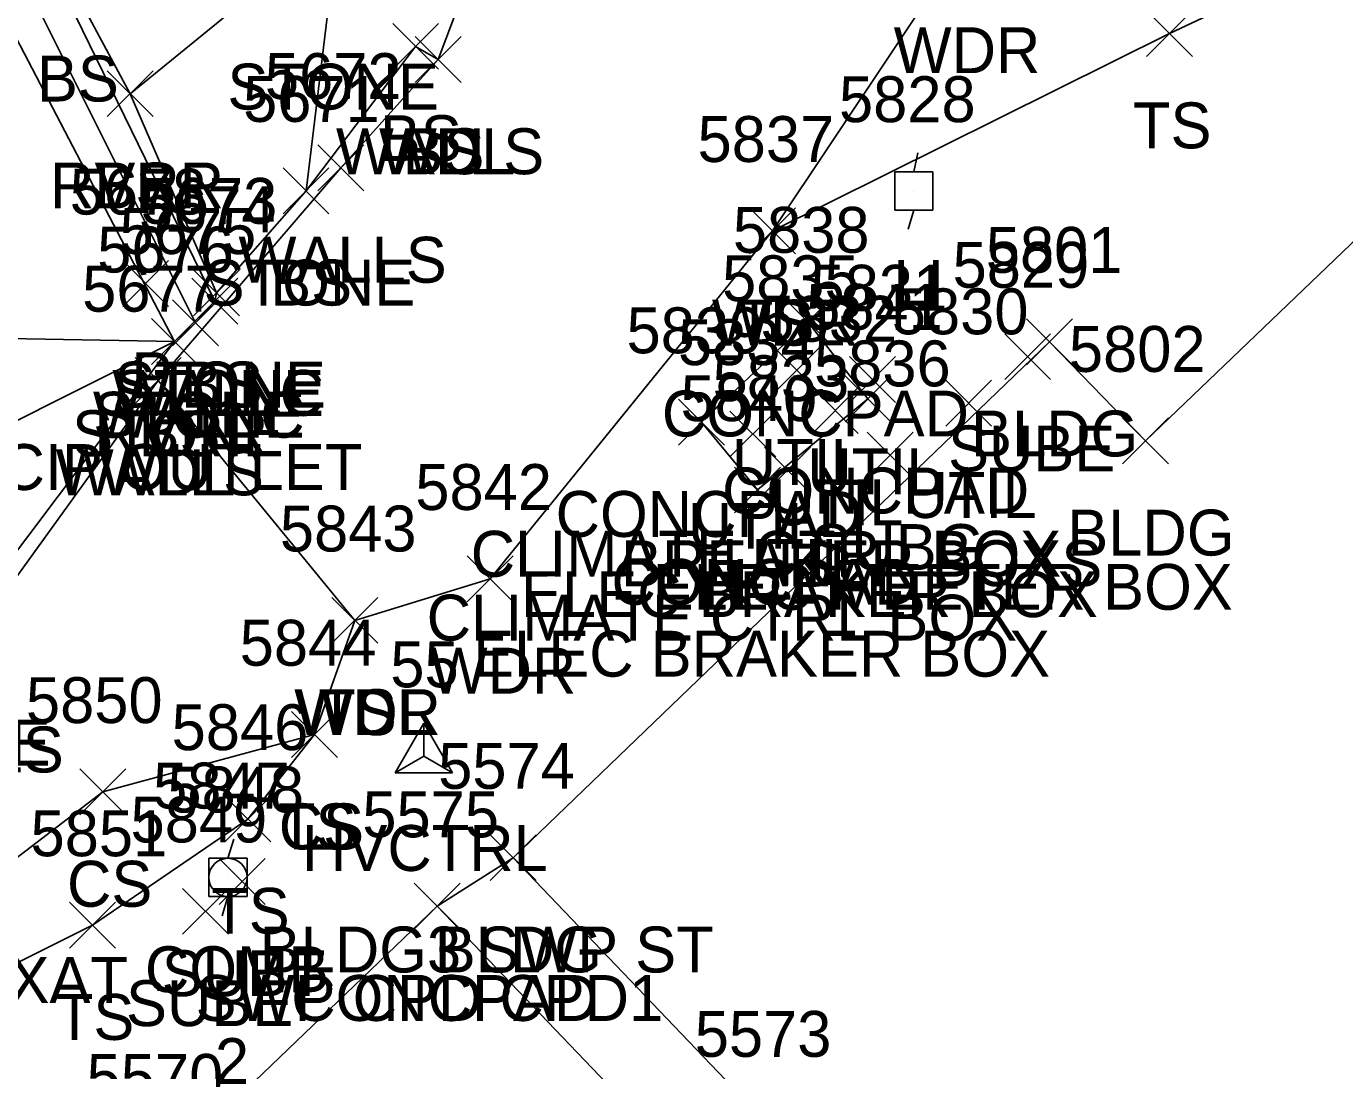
# Model space of a CAD drawing. Extents: x 1618146 to 1620418, y 640749 to 641927.
# Drawn here: x 1620120.5 to 1620177.9, y 641215.6 to 641261.1 of the extents above; entities that cross this region are included whole.
import ezdxf

# ---------------------------------------------------------------- set-up
doc = ezdxf.new("R2010")
doc.units = 0
for name, color, linetype in [('C_A', 7, 'Continuous'), ('C_C', 7, 'Continuous'), ('C_I', 7, 'Continuous'), ('CPSM', 7, 'Continuous'), ('D_A', 7, 'Continuous'), ('D_C', 7, 'Continuous'), ('D_I', 7, 'Continuous'), ('D_TIC', 7, 'Continuous'), ('L_A', 7, 'Continuous'), ('L_I', 7, 'Continuous'), ('L_TIC', 7, 'Continuous'), ('LASF', 7, 'Continuous'), ('LAWA', 7, 'Continuous'), ('LAWE', 7, 'Continuous'), ('LBC', 7, 'Continuous'), ('LELB', 7, 'Continuous'), ('LS', 7, 'Continuous'), ('LW', 7, 'Continuous'), ('LWS', 7, 'Continuous'), ('R_A', 7, 'Continuous'), ('R_I', 7, 'Continuous'), ('R_TIC', 7, 'Continuous'), ('RSW', 7, 'Continuous'), ('U_A', 7, 'Continuous'), ('U_C', 7, 'Continuous'), ('U_I', 7, 'Continuous'), ('U_TIC', 7, 'Continuous'), ('UDEFAULT', 7, 'Continuous'), ('ULP', 7, 'Continuous'), ('UP', 7, 'Continuous')]:
    doc.layers.add(name, color=color, linetype=linetype)

msp = doc.modelspace()

# ---------------------------------------------------------------- linework, layer by layer
at = {"layer": 'CPSM'}
for p, q in [((1620136.538, 641228.601), (1620137.788, 641230.766)), ((1620139.038, 641228.601), (1620137.788, 641230.766)), ((1620137.788, 641229.322), (1620137.788, 641230.766)), ((1620136.538, 641228.601), (1620137.788, 641229.322)), ((1620137.788, 641229.322), (1620137.788, 641229.322)), ((1620137.788, 641229.322), (1620139.038, 641228.601)), ((1620136.538, 641228.601), (1620139.038, 641228.601))]:
    msp.add_line(p, q, dxfattribs=at)
at = {"layer": 'D_TIC'}
for points in [[(1620124.672, 641248.918), (1620126.672, 641250.918)], [(1620126.672, 641248.918), (1620124.672, 641250.918)]]:
    msp.add_lwpolyline(points, dxfattribs=at)
at = {"layer": 'L_TIC'}
for points in [[(1620169.25, 641259.802), (1620171.25, 641261.802)], [(1620171.25, 641259.802), (1620169.25, 641261.802)], [(1620136.427, 641259.244), (1620138.427, 641261.244)], [(1620138.427, 641259.244), (1620136.427, 641261.244)], [(1620137.412, 641258.674), (1620139.412, 641260.674)], [(1620139.412, 641258.674), (1620137.412, 641260.674)], [(1620137.412, 641258.674), (1620139.412, 641260.674)], [(1620139.412, 641258.674), (1620137.412, 641260.674)], [(1620137.412, 641258.674), (1620139.412, 641260.674)], [(1620139.412, 641258.674), (1620137.412, 641260.674)], [(1620123.997, 641257.183), (1620125.997, 641259.183)], [(1620125.997, 641257.183), (1620123.997, 641259.183)], [(1620123.997, 641257.183), (1620125.997, 641259.183)], [(1620125.997, 641257.183), (1620123.997, 641259.183)], [(1620133.17, 641253.949), (1620135.17, 641255.949)], [(1620135.17, 641253.949), (1620133.17, 641255.949)], [(1620131.653, 641252.954), (1620133.653, 641254.954)], [(1620133.653, 641252.954), (1620131.653, 641254.954)], [(1620131.653, 641252.954), (1620133.653, 641254.954)], [(1620133.653, 641252.954), (1620131.653, 641254.954)], [(1620151.961, 641251.207), (1620153.961, 641253.207)], [(1620153.961, 641251.207), (1620151.961, 641253.207)], [(1620151.961, 641251.207), (1620153.961, 641253.207)], [(1620153.961, 641251.207), (1620151.961, 641253.207)], [(1620127.684, 641248.148), (1620129.684, 641250.148)], [(1620129.684, 641248.148), (1620127.684, 641250.148)], [(1620127.684, 641248.148), (1620129.684, 641250.148)], [(1620129.684, 641248.148), (1620127.684, 641250.148)], [(1620127.761, 641248.512), (1620129.761, 641250.512)], [(1620129.761, 641248.512), (1620127.761, 641250.512)], [(1620127.761, 641248.512), (1620129.761, 641250.512)], [(1620129.761, 641248.512), (1620127.761, 641250.512)], [(1620126.842, 641247.197), (1620128.842, 641249.197)], [(1620128.842, 641247.197), (1620126.842, 641249.197)], [(1620126.842, 641247.197), (1620128.842, 641249.197)], [(1620128.842, 641247.197), (1620126.842, 641249.197)], [(1620153.5, 641247.251), (1620155.5, 641249.251)], [(1620155.5, 641247.251), (1620153.5, 641249.251)], [(1620153.5, 641247.251), (1620155.5, 641249.251)], [(1620155.5, 641247.251), (1620153.5, 641249.251)], [(1620125.924, 641246.392), (1620127.924, 641248.392)], [(1620127.924, 641246.392), (1620125.924, 641248.392)], [(1620125.924, 641246.392), (1620127.924, 641248.392)], [(1620127.924, 641246.392), (1620125.924, 641248.392)], [(1620125.924, 641246.392), (1620127.924, 641248.392)], [(1620127.924, 641246.392), (1620125.924, 641248.392)], [(1620125.924, 641246.392), (1620127.924, 641248.392)], [(1620127.924, 641246.392), (1620125.924, 641248.392)], [(1620164.022, 641246.378), (1620166.022, 641248.378)], [(1620166.022, 641246.378), (1620164.022, 641248.378)], [(1620125.214, 641244.687), (1620127.214, 641246.687)], [(1620127.214, 641244.687), (1620125.214, 641246.687)], [(1620125.214, 641244.687), (1620127.214, 641246.687)], [(1620127.214, 641244.687), (1620125.214, 641246.687)], [(1620156.121, 641243.894), (1620158.121, 641245.894)], [(1620158.121, 641243.894), (1620156.121, 641245.894)], [(1620156.121, 641243.894), (1620158.121, 641245.894)], [(1620158.121, 641243.894), (1620156.121, 641245.894)], [(1620148.876, 641242.874), (1620150.876, 641244.874)], [(1620150.876, 641242.874), (1620148.876, 641244.874)], [(1620168.209, 641242.063), (1620170.209, 641244.063)], [(1620170.209, 641242.063), (1620168.209, 641244.063)], [(1620151.306, 641239.919), (1620153.306, 641241.919)], [(1620153.306, 641239.919), (1620151.306, 641241.919)], [(1620139.672, 641236.047), (1620141.672, 641238.047)], [(1620141.672, 641236.047), (1620139.672, 641238.047)], [(1620133.776, 641234.239), (1620135.776, 641236.239)], [(1620135.776, 641234.239), (1620133.776, 641236.239)], [(1620133.776, 641234.239), (1620135.776, 641236.239)], [(1620135.776, 641234.239), (1620133.776, 641236.239)], [(1620133.776, 641234.239), (1620135.776, 641236.239)], [(1620135.776, 641234.239), (1620133.776, 641236.239)], [(1620132.025, 641229.264), (1620134.025, 641231.264)], [(1620134.025, 641229.264), (1620132.025, 641231.264)], [(1620132.025, 641229.264), (1620134.025, 641231.264)], [(1620134.025, 641229.264), (1620132.025, 641231.264)], [(1620122.806, 641226.765), (1620124.806, 641228.765)], [(1620124.806, 641226.765), (1620122.806, 641228.765)], [(1620129.116, 641225.586), (1620131.116, 641227.586)], [(1620131.116, 641225.586), (1620129.116, 641227.586)], [(1620140.669, 641223.901), (1620142.669, 641225.901)], [(1620142.669, 641223.901), (1620140.669, 641225.901)], [(1620137.364, 641221.789), (1620139.364, 641223.789)], [(1620139.364, 641221.789), (1620137.364, 641223.789)], [(1620137.364, 641221.789), (1620139.364, 641223.789)], [(1620139.364, 641221.789), (1620137.364, 641223.789)], [(1620122.352, 641220.964), (1620124.352, 641222.964)], [(1620124.352, 641220.964), (1620122.352, 641222.964)]]:
    msp.add_lwpolyline(points, dxfattribs=at)
at = {"layer": 'LASF'}
msp.add_lwpolyline([(1620199.521, 641313.799), (1620179.367, 641298.383), (1620161.035, 641285.687), (1620141.172, 641269.891), (1620133.686, 641262.491), (1620132.653, 641253.954), (1620128.761, 641249.512), (1620128.684, 641249.148), (1620127.842, 641248.197), (1620126.924, 641247.392), (1620116.779, 641233.91), (1620111.433, 641226.039)], dxfattribs=at)
at = {"layer": 'LAWA'}
for points in [[(1620200.288, 641313.037), (1620179.156, 641297.147), (1620161.988, 641285.049), (1620141.946, 641269.083), (1620138.412, 641259.674)], [(1620208.075, 641304.38), (1620197.125, 641293.977), (1620183.248, 641283.239), (1620177.429, 641277.782), (1620160.878, 641264.077), (1620152.961, 641252.207), (1620140.672, 641237.047), (1620134.776, 641235.239)], [(1620126.214, 641245.687), (1620134.776, 641235.239)]]:
    msp.add_lwpolyline(points, dxfattribs=at)
at = {"layer": 'LAWE'}
for points in [[(1620197.76, 641315.891), (1620177.713, 641299.582), (1620159.429, 641288.631), (1620140.112, 641270.502), (1620124.997, 641258.183)], [(1620126.924, 641247.392), (1620111.117, 641239.46), (1620109.41, 641236.163), (1620101.636, 641234.759), (1620084.088, 641235.913), (1620071.67, 641229.784), (1620042.737, 641224.388), (1620037.792, 641222.07), (1620025.57, 641215.03), (1620021.304, 641209.771), (1620016.061, 641211.085), (1620004.818, 641210.958), (1619989.454, 641201.04), (1619976.614, 641195.505), (1619948.377, 641191.059)]]:
    msp.add_lwpolyline(points, dxfattribs=at)
at = {"layer": 'LBC'}
msp.add_lwpolyline([(1620215.058, 641244.302), (1620205.976, 641235.712), (1620202.677, 641232.585), (1620189.499, 641220.107), (1620199.083, 641211.828), (1620201.415, 641213.808), (1620202.472, 641212.521), (1620205.827, 641209.331), (1620206.941, 641208.229), (1620204.756, 641205.896), (1620213.685, 641196.392), (1620197.139, 641180.509), (1620189.981, 641173.967), (1620166.556, 641198.685), (1620162.715, 641202.828), (1620152.839, 641213.225), (1620141.669, 641224.901), (1620165.022, 641247.378), (1620169.209, 641243.063), (1620193.587, 641266.433)], dxfattribs=at)
at = {"layer": 'LELB'}
for points in [[(1620096.253, 641317.327), (1620100.674, 641308.519), (1620103.321, 641303.565), (1620106.623, 641296.021), (1620112.214, 641284.502), (1620118.291, 641271.621), (1620119.66, 641268.577), (1620122.496, 641262.842), (1620124.997, 641258.183), (1620128.761, 641249.512)], [(1620094.279, 641315.291), (1620094.86, 641313.595), (1620100.39, 641301.82), (1620102.742, 641293.774), (1620108.781, 641281.996), (1620114.966, 641271.602), (1620116.112, 641268.122), (1620126.924, 641247.392)], [(1620214.968, 641229.37), (1620217.367, 641235.303), (1620219.618, 641240.432), (1620202.327, 641265.422), (1620193.89, 641269.411), (1620188.385, 641269.337), (1620170.25, 641260.802), (1620152.961, 641252.207)], [(1620138.412, 641259.674), (1620137.427, 641260.244), (1620132.653, 641253.954)], [(1620126.924, 641247.392), (1620111.61, 641247.659), (1620106.398, 641242.54), (1620098.527, 641237.323), (1620084.828, 641239.216), (1620069.098, 641232.991), (1620064.278, 641237.198), (1620039.166, 641227.389), (1620035.445, 641222.864), (1620023.476, 641219.069), (1620012.158, 641216.975), (1620003.405, 641213.467), (1619988.117, 641206.058), (1619975.419, 641196.769), (1619947.495, 641194.474)], [(1620134.776, 641235.239), (1620133.025, 641230.264), (1620130.116, 641226.586), (1620123.352, 641221.964), (1620117.056, 641218.812), (1620115.45, 641219.995), (1620111.752, 641225.001)], [(1620133.025, 641230.264), (1620123.806, 641227.765), (1620116.902, 641222.479)]]:
    msp.add_lwpolyline(points, dxfattribs=at)
at = {"layer": 'LS'}
for points in [[(1620154.5, 641248.251), (1620149.876, 641243.874), (1620152.306, 641240.919), (1620157.121, 641244.894)], [(1620154.5, 641248.251), (1620157.121, 641244.894)], [(1620147.247, 641189.39), (1620126.449, 641211.351), (1620138.364, 641222.789)], [(1620147.247, 641189.39), (1620152.297, 641193.8), (1620159.631, 641200.696), (1620150.572, 641210.022), (1620138.364, 641222.789)]]:
    msp.add_lwpolyline(points, dxfattribs=at)
at = {"layer": 'LW'}
for points in [[(1620094.159, 641317.06), (1620095.404, 641313.811), (1620098.931, 641307.164), (1620101.469, 641302.424), (1620101.685, 641302.19), (1620104.659, 641294.911), (1620110.165, 641282.857), (1620115.766, 641272.34), (1620117.527, 641268.841), (1620127.842, 641248.197)], [(1620096.2, 641316.747), (1620096.139, 641316.39), (1620100.572, 641308.035), (1620102.909, 641303.231), (1620103.256, 641302.814), (1620106.321, 641295.796), (1620112.201, 641283.797), (1620117.831, 641272.034), (1620119.282, 641268.399), (1620128.684, 641249.148)]]:
    msp.add_lwpolyline(points, dxfattribs=at)
at = {"layer": 'LWS'}
msp.add_lwpolyline([(1620138.412, 641259.674), (1620134.17, 641254.949), (1620126.214, 641245.687), (1620117.496, 641233.613), (1620111.433, 641226.039)], dxfattribs=at)
at = {"layer": 'R_TIC'}
for points in [[(1620140.669, 641223.901), (1620142.669, 641225.901)], [(1620142.669, 641223.901), (1620140.669, 641225.901)], [(1620137.364, 641221.789), (1620139.364, 641223.789)], [(1620139.364, 641221.789), (1620137.364, 641223.789)]]:
    msp.add_lwpolyline(points, dxfattribs=at)
at = {"layer": 'RSW'}
msp.add_lwpolyline([(1620141.669, 641224.901), (1620138.364, 641222.789)], dxfattribs=at)
at = {"layer": 'U_TIC'}
for points in [[(1620163.073, 641245.728), (1620165.073, 641247.728)], [(1620165.073, 641245.728), (1620163.073, 641247.728)], [(1620157.087, 641241.432), (1620159.087, 641243.432)], [(1620159.087, 641241.432), (1620157.087, 641243.432)], [(1620128.876, 641222.869), (1620130.876, 641224.869)], [(1620130.876, 641222.869), (1620128.876, 641224.869)], [(1620127.28, 641221.564), (1620129.28, 641223.564)], [(1620129.28, 641221.564), (1620127.28, 641223.564)]]:
    msp.add_lwpolyline(points, dxfattribs=at)
at = {"layer": 'UDEFAULT'}
for points in [[(1620153.028, 641245.14), (1620155.028, 641247.14)], [(1620155.028, 641245.14), (1620153.028, 641247.14)], [(1620156.313, 641244.728), (1620158.313, 641246.728)], [(1620158.313, 641244.728), (1620156.313, 641246.728)], [(1620160.505, 641243.7), (1620162.505, 641245.7)], [(1620162.505, 641243.7), (1620160.505, 641245.7)], [(1620154.699, 641243.38), (1620156.699, 641245.38)], [(1620156.699, 641243.38), (1620154.699, 641245.38)], [(1620151.11, 641242.359), (1620153.11, 641244.359)], [(1620153.11, 641242.359), (1620151.11, 641244.359)], [(1620152.615, 641240.787), (1620154.615, 641242.787)], [(1620154.615, 641240.787), (1620152.615, 641242.787)]]:
    msp.add_lwpolyline(points, dxfattribs=at)
at = {"layer": 'ULP'}
for p, q in [((1620159.285, 641255.609), (1620159.118, 641254.775)), ((1620158.285, 641253.109), (1620158.285, 641254.775)), ((1620158.285, 641254.775), (1620159.952, 641254.775)), ((1620159.952, 641254.775), (1620159.952, 641253.109)), ((1620159.118, 641253.942), (1620159.118, 641253.942)), ((1620159.952, 641253.109), (1620158.285, 641253.109)), ((1620158.868, 641252.275), (1620159.118, 641253.109))]:
    msp.add_line(p, q, dxfattribs=at)
at = {"layer": 'UP'}
for p, q in [((1620129.504, 641225.708), (1620129.254, 641224.874)), ((1620128.42, 641223.208), (1620128.42, 641224.874)), ((1620128.42, 641224.874), (1620130.087, 641224.874)), ((1620130.087, 641224.874), (1620130.087, 641223.208)), ((1620129.254, 641224.041), (1620129.254, 641224.041)), ((1620130.087, 641223.208), (1620128.42, 641223.208)), ((1620129.004, 641222.374), (1620129.254, 641223.208))]:
    msp.add_line(p, q, dxfattribs=at)
msp.add_circle((1620129.254, 641224.041), 0.833, dxfattribs=at)

# ---------------------------------------------------------------- texts
at = {"layer": 'C_A'}
msp.add_text('HVCTRL', height=2, dxfattribs=at).set_placement((1620132.481, 641224.322))
at = {"layer": 'C_C'}
msp.add_text('BM49=CGS DISK IN CONC XAT', height=2, dxfattribs=at).set_placement((1620085.59, 641218.573))
at = {"layer": 'C_I'}
msp.add_text('55', height=2, dxfattribs=at).set_placement((1620136.324, 641232.322))
at = {"layer": 'D_A'}
msp.add_text('P', height=2, dxfattribs=at).set_placement((1620125.05, 641244.918))
at = {"layer": 'D_C'}
msp.add_text('12"CIP OUTLET', height=2, dxfattribs=at).set_placement((1620115.429, 641240.918))
at = {"layer": 'D_I'}
msp.add_text('5678', height=2, dxfattribs=at).set_placement((1620122.365, 641252.918))
at = {"layer": 'L_A'}
for s, p in [('WDR', (1620158.24, 641259.077)), ('BS', (1620120.937, 641257.842)), ('BS', (1620120.937, 641257.842)), ('STONE', (1620129.23, 641257.491)), ('TS', (1620168.66, 641255.802)), ('BS', (1620135.868, 641255.244)), ('WALLS', (1620133.956, 641254.674)), ('WDL', (1620135.83, 641254.674)), ('BS', (1620136.853, 641254.674)), ('BS', (1620123.438, 641253.183)), ('RVRR', (1620121.509, 641253.183)), ('WALLS', (1620129.713, 641249.949)), ('STONE', (1620128.196, 641248.954)), ('BS', (1620131.094, 641248.954)), ('WDR', (1620150.323, 641247.207)), ('TS', (1620151.37, 641247.207)), ('WALLC', (1620124.219, 641244.148)), ('STONE', (1620124.227, 641244.148)), ('STONE', (1620124.304, 641244.512)), ('BS', (1620127.202, 641244.512)), ('WALLC', (1620123.377, 641243.197)), ('STONE', (1620123.385, 641243.197)), ('CONCPAD', (1620148.145, 641243.251)), ('CONCPAD', (1620148.145, 641243.251)), ('STONE', (1620122.467, 641242.392)), ('RVRR', (1620123.436, 641242.392)), ('BS', (1620125.365, 641242.392)), ('BS', (1620125.365, 641242.392)), ('BLDG', (1620161.612, 641242.378)), ('WALLS', (1620121.757, 641240.687)), ('WDL', (1620123.631, 641240.687)), ('CONCPAD', (1620150.767, 641239.894)), ('CONCPAD', (1620150.767, 641239.894)), ('CONCPAD', (1620143.522, 641238.874)), ('BLDG', (1620165.8, 641238.063)), ('CONCPAD', (1620145.952, 641235.919)), ('WDR', (1620138.034, 641232.047)), ('WDR', (1620132.138, 641230.239)), ('WDL', (1620132.193, 641230.239)), ('TS', (1620133.186, 641230.239)), ('STONE', (1620112.322, 641228.91)), ('WALLS', (1620113.04, 641228.613)), ('TS', (1620131.435, 641225.264)), ('CS', (1620131.466, 641225.264)), ('CS', (1620122.247, 641222.765)), ('TS', (1620128.526, 641221.586)), ('BLDG', (1620138.26, 641219.901)), ('CONCPAD', (1620132.01, 641217.789)), ('CONCPAD', (1620132.01, 641217.789)), ('TS', (1620121.761, 641216.964))]:
    msp.add_text(s, height=2, dxfattribs=at).set_placement(p)
at = {"layer": 'L_I'}
for s, p in [('5672', (1620130.863, 641257.949)), ('5671', (1620129.913, 641256.954)), ('5671', (1620129.913, 641256.954)), ('5837', (1620149.701, 641255.207)), ('5837', (1620149.701, 641255.207)), ('5674', (1620125.377, 641252.148)), ('5674', (1620125.377, 641252.148)), ('5673', (1620125.454, 641252.512)), ('5673', (1620125.454, 641252.512)), ('5675', (1620124.535, 641251.197)), ('5675', (1620124.535, 641251.197)), ('5838', (1620151.24, 641251.251)), ('5838', (1620151.24, 641251.251)), ('5676', (1620123.562, 641250.392)), ('5676', (1620123.562, 641250.392)), ('5676', (1620123.562, 641250.392)), ('5676', (1620123.562, 641250.392)), ('5801', (1620162.25, 641250.378)), ('5677', (1620122.907, 641248.687)), ('5677', (1620122.907, 641248.687)), ('5841', (1620154.429, 641247.894)), ('5841', (1620154.429, 641247.894)), ('5839', (1620146.609, 641246.874)), ('5802', (1620165.87, 641246.063)), ('5840', (1620148.96, 641243.919)), ('5842', (1620137.412, 641240.047)), ('5843', (1620131.516, 641238.239)), ('5843', (1620131.516, 641238.239)), ('5843', (1620131.516, 641238.239)), ('5844', (1620129.766, 641233.264)), ('5844', (1620129.766, 641233.264)), ('5850', (1620120.459, 641230.765)), ('5846', (1620126.802, 641229.586)), ('5574', (1620138.409, 641227.901)), ('5575', (1620135.105, 641225.789)), ('5575', (1620135.105, 641225.789)), ('5851', (1620120.659, 641224.964)), ('5573', (1620149.579, 641216.225)), ('5570', (1620123.102, 641214.351))]:
    msp.add_text(s, height=2, dxfattribs=at).set_placement(p)
at = {"layer": 'R_A'}
for s, p in [('BLDG3 SWP ST', (1620130.638, 641219.901)), ('SWP CPD CPD1', (1620127.845, 641217.789))]:
    msp.add_text(s, height=2, dxfattribs=at).set_placement(p)
at = {"layer": 'R_I'}
for s, p in [('5574', (1620138.409, 641227.901)), ('5575', (1620135.105, 641225.789)), ('5573', (1620149.579, 641216.225))]:
    msp.add_text(s, height=2, dxfattribs=at).set_placement(p)
at = {"layer": 'U_A'}
for s, p in [('LI', (1620158.221, 641248.942)), ('SUBE', (1620160.608, 641241.728)), ('UTIL', (1620151.194, 641241.14)), ('UTIL', (1620154.479, 641240.728)), ('UTIL', (1620158.67, 641239.7)), ('UTIL', (1620152.865, 641239.38)), ('UTIL', (1620149.275, 641238.359)), ('SUBG', (1620154.615, 641237.432)), ('UTIL', (1620150.78, 641236.787)), ('COMB', (1620125.639, 641219.041)), ('SUBT', (1620126.372, 641218.869)), ('SUBE', (1620124.816, 641217.564))]:
    msp.add_text(s, height=2, dxfattribs=at).set_placement(p)
at = {"layer": 'U_C'}
for s, p in [('CLIMATE CTRL BOX', (1620139.824, 641237.14)), ('BREAKER BOXS', (1620146.368, 641236.728)), ('ELEC BRAKER BOX', (1620142.015, 641235.38)), ('ELEC MEETER BOX', (1620147.741, 641235.7)), ('CLIMATE CTRL BOX', (1620137.906, 641234.359)), ('ELEC BRAKER BOX', (1620139.93, 641232.787)), ('2', (1620128.687, 641215.041))]:
    msp.add_text(s, height=2, dxfattribs=at).set_placement(p)
at = {"layer": 'U_I'}
for s, p in [('5828', (1620155.859, 641256.942)), ('5829', (1620160.805, 641249.728)), ('5835', (1620150.769, 641249.14)), ('5831', (1620154.62, 641248.728)), ('5830', (1620158.159, 641247.7)), ('5832', (1620152.44, 641247.38)), ('5834', (1620148.85, 641246.359)), ('5836', (1620154.772, 641245.432)), ('5833', (1620150.355, 641244.787)), ('5847', (1620125.994, 641227.041)), ('5848', (1620126.616, 641226.869)), ('5849', (1620125.013, 641225.564))]:
    msp.add_text(s, height=2, dxfattribs=at).set_placement(p)

doc.saveas('drawing.dxf')
